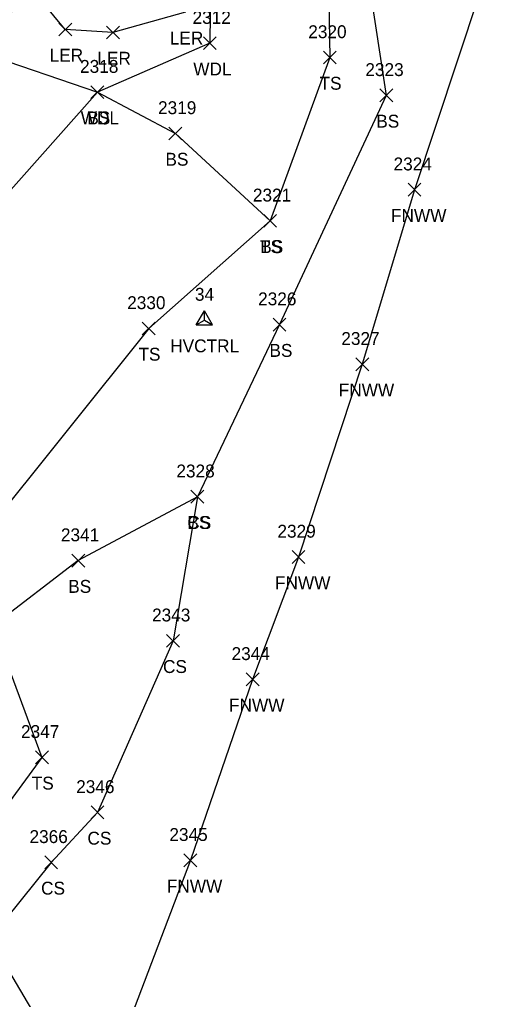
# Model space of a CAD drawing. Extents: x 1483143 to 1488182, y 802902 to 807581.
# Drawn here: x 1487912.6 to 1487987.2, y 806252.6 to 806404.6 of the extents above; entities that cross this region are included whole.
import ezdxf

# ---------------------------------------------------------------- set-up
doc = ezdxf.new("R2010")
doc.units = 0
for name, color, linetype in [('C_A', 7, 'Continuous'), ('C_I', 7, 'Continuous'), ('CPSM', 7, 'Continuous'), ('L_A', 7, 'Continuous'), ('L_I', 7, 'Continuous'), ('L_TIC', 7, 'Continuous'), ('LARO', 7, 'Continuous'), ('LAWA', 7, 'Continuous'), ('LELB', 7, 'Continuous'), ('LFNC', 7, 'Continuous')]:
    doc.layers.add(name, color=color, linetype=linetype)

msp = doc.modelspace()

# ---------------------------------------------------------------- linework, layer by layer
at = {"layer": 'CPSM'}
for p, q in [((1487940.02, 806357.27), (1487941.27, 806359.43)), ((1487942.52, 806357.27), (1487941.27, 806359.43)), ((1487941.27, 806357.99), (1487941.27, 806359.43)), ((1487940.02, 806357.27), (1487941.27, 806357.99)), ((1487940.02, 806357.27), (1487942.52, 806357.27)), ((1487941.27, 806357.99), (1487941.27, 806357.99)), ((1487941.27, 806357.99), (1487942.52, 806357.27))]:
    msp.add_line(p, q, dxfattribs=at)
at = {"layer": 'L_TIC'}
for points in [[(1487918.67, 806402.09), (1487920.67, 806404.09)], [(1487920.67, 806402.09), (1487918.67, 806404.09)], [(1487926.08, 806401.62), (1487928.08, 806403.62)], [(1487928.08, 806401.62), (1487926.08, 806403.62)], [(1487941.13, 806399.96), (1487943.13, 806401.96)], [(1487943.13, 806399.96), (1487941.13, 806401.96)], [(1487959.75, 806397.74), (1487961.75, 806399.74)], [(1487961.75, 806397.74), (1487959.75, 806399.74)], [(1487923.66, 806392.36), (1487925.66, 806394.36)], [(1487925.66, 806392.36), (1487923.66, 806394.36)], [(1487923.66, 806392.36), (1487925.66, 806394.36)], [(1487925.66, 806392.36), (1487923.66, 806394.36)], [(1487968.53, 806391.86), (1487970.53, 806393.86)], [(1487970.53, 806391.86), (1487968.53, 806393.86)], [(1487935.78, 806385.95), (1487937.78, 806387.95)], [(1487937.78, 806385.95), (1487935.78, 806387.95)], [(1487972.91, 806377.22), (1487974.91, 806379.22)], [(1487974.91, 806377.22), (1487972.91, 806379.22)], [(1487950.5, 806372.39), (1487952.5, 806374.39)], [(1487952.5, 806372.39), (1487950.5, 806374.39)], [(1487950.5, 806372.39), (1487952.5, 806374.39)], [(1487952.5, 806372.39), (1487950.5, 806374.39)], [(1487931.63, 806355.69), (1487933.63, 806357.69)], [(1487933.63, 806355.69), (1487931.63, 806357.69)], [(1487951.94, 806356.28), (1487953.94, 806358.28)], [(1487953.94, 806356.28), (1487951.94, 806358.28)], [(1487964.8, 806350.13), (1487966.8, 806352.13)], [(1487966.8, 806350.13), (1487964.8, 806352.13)], [(1487939.19, 806329.57), (1487941.19, 806331.57)], [(1487941.19, 806329.57), (1487939.19, 806331.57)], [(1487939.19, 806329.57), (1487941.19, 806331.57)], [(1487941.19, 806329.57), (1487939.19, 806331.57)], [(1487954.89, 806320.22), (1487956.89, 806322.22)], [(1487956.89, 806320.22), (1487954.89, 806322.22)], [(1487920.69, 806319.66), (1487922.69, 806321.66)], [(1487922.69, 806319.66), (1487920.69, 806321.66)], [(1487935.41, 806307.22), (1487937.41, 806309.22)], [(1487937.41, 806307.22), (1487935.41, 806309.22)], [(1487947.76, 806301.23), (1487949.76, 806303.23)], [(1487949.76, 806301.23), (1487947.76, 806303.23)], [(1487915.06, 806289.13), (1487917.06, 806291.13)], [(1487917.06, 806289.13), (1487915.06, 806291.13)], [(1487923.68, 806280.58), (1487925.68, 806282.58)], [(1487925.68, 806280.58), (1487923.68, 806282.58)], [(1487916.48, 806272.83), (1487918.48, 806274.83)], [(1487918.48, 806272.83), (1487916.48, 806274.83)], [(1487938.1, 806273.15), (1487940.1, 806275.15)], [(1487940.1, 806273.15), (1487938.1, 806275.15)]]:
    msp.add_lwpolyline(points, dxfattribs=at)
at = {"layer": 'LARO'}
msp.add_lwpolyline([(1487938.33, 806405.75), (1487927.08, 806402.62), (1487919.67, 806403.09), (1487914.11, 806409.79), (1487906.78, 806399.47), (1487893.33, 806381.44), (1487887.6, 806370.68), (1487880.83, 806355.03), (1487873.24, 806335.95), (1487862.81, 806310.84), (1487845.31, 806291.53), (1487837.06, 806275.13), (1487830.31, 806264.75), (1487822.51, 806259.14), (1487820.37, 806244.37)], dxfattribs=at)
at = {"layer": 'LAWA'}
msp.add_lwpolyline([(1487942.37, 806424.18), (1487942.13, 806400.96), (1487924.66, 806393.36), (1487906.74, 806373.16), (1487899.59, 806370.18), (1487890.83, 806350.54), (1487893.79, 806329.46), (1487876.29, 806319.09), (1487863.09, 806294.65), (1487840.52, 806269.33), (1487843.55, 806264.22), (1487833.59, 806259.9), (1487830.72, 806250.51), (1487828.92, 806235.37), (1487823.44, 806218.85), (1487816.5, 806198.3), (1487812.31, 806191.59), (1487811.73, 806182.07)], dxfattribs=at)
at = {"layer": 'LELB'}
for points in [[(1487959.91, 806445.22), (1487960.75, 806398.74), (1487951.5, 806373.39), (1487932.63, 806356.69), (1487906.84, 806324.5), (1487908.42, 806310.52), (1487916.06, 806290.13), (1487905.83, 806276.22)], [(1487966.07, 806415.18), (1487969.53, 806392.86), (1487952.94, 806357.28), (1487940.19, 806330.57), (1487921.69, 806320.66), (1487908.42, 806310.52), (1487904.09, 806299.8)], [(1487906.78, 806399.47), (1487924.66, 806393.36), (1487936.78, 806386.95), (1487951.5, 806373.39)], [(1487940.19, 806330.57), (1487936.41, 806308.22), (1487924.68, 806281.58), (1487917.48, 806273.83), (1487907.89, 806261.98), (1487917.31, 806246.1), (1487904.77, 806206.09), (1487890.85, 806175.33)]]:
    msp.add_lwpolyline(points, dxfattribs=at)
at = {"layer": 'LFNC'}
msp.add_lwpolyline([(1487987.25, 806418.51), (1487973.91, 806378.22), (1487965.8, 806351.13), (1487955.89, 806321.22), (1487948.76, 806302.23), (1487939.1, 806274.15), (1487927.43, 806243.4), (1487914.16, 806209.81), (1487898.86, 806171.16), (1487882.05, 806128.03), (1487871.82, 806101.28), (1487863.45, 806079.83), (1487853.77, 806056.92)], dxfattribs=at)

# ---------------------------------------------------------------- texts
at = {"layer": 'C_A'}
msp.add_text('HVCTRL', height=2, dxfattribs=at).set_placement((1487935.97, 806352.99))
at = {"layer": 'C_I'}
msp.add_text('34', height=2, dxfattribs=at).set_placement((1487939.81, 806360.99))
at = {"layer": 'L_A'}
for s, p in [('LER', (1487935.91, 806400.75)), ('LER', (1487917.25, 806398.09)), ('LER', (1487924.66, 806397.62)), ('WDL', (1487939.55, 806395.96)), ('TS', (1487959.16, 806393.74)), ('WDL', (1487922.08, 806388.36)), ('BS', (1487923.1, 806388.36)), ('BS', (1487967.97, 806387.86)), ('BS', (1487935.23, 806381.95)), ('FNWW', (1487970.25, 806373.22)), ('TS', (1487949.91, 806368.39)), ('BS', (1487949.95, 806368.39)), ('BS', (1487951.38, 806352.28)), ('TS', (1487931.04, 806351.69)), ('FNWW', (1487962.14, 806346.13)), ('CS', (1487938.63, 806325.57)), ('BS', (1487938.63, 806325.57)), ('BS', (1487920.14, 806315.66)), ('FNWW', (1487952.24, 806316.22)), ('CS', (1487934.85, 806303.22)), ('FNWW', (1487945.1, 806297.23)), ('TS', (1487914.47, 806285.13)), ('CS', (1487923.12, 806276.58)), ('CS', (1487915.92, 806268.83)), ('FNWW', (1487935.45, 806269.15))]:
    msp.add_text(s, height=2, dxfattribs=at).set_placement(p)
at = {"layer": 'L_I'}
for s, p in [('2312', (1487939.44, 806403.96)), ('2320', (1487957.41, 806401.74)), ('2318', (1487921.97, 806396.36)), ('2318', (1487921.97, 806396.36)), ('2323', (1487966.27, 806395.86)), ('2319', (1487934.08, 806389.95)), ('2324', (1487970.65, 806381.22)), ('2321', (1487948.81, 806376.39)), ('2321', (1487948.81, 806376.39)), ('2330', (1487929.29, 806359.69)), ('2326', (1487949.62, 806360.28)), ('2327', (1487962.54, 806354.13)), ('2328', (1487936.93, 806333.57)), ('2328', (1487936.93, 806333.57)), ('2341', (1487919, 806323.66)), ('2329', (1487952.62, 806324.22)), ('2343', (1487933.15, 806311.22)), ('2344', (1487945.5, 806305.23)), ('2347', (1487912.8, 806293.13)), ('2346', (1487921.37, 806284.58)), ('2366', (1487914.12, 806276.83)), ('2345', (1487935.84, 806277.15))]:
    msp.add_text(s, height=2, dxfattribs=at).set_placement(p)

doc.saveas('drawing.dxf')
